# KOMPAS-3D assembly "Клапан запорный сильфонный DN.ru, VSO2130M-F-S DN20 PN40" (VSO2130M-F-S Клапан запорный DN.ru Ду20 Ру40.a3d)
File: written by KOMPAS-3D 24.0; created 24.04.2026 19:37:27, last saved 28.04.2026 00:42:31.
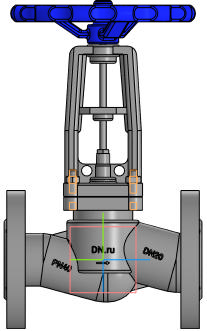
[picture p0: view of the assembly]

Document properties: Автор: DN.ru; Полное имя файла: C:\Работа\ГОТОВЫЕ ИСХОДНИКИ\VSO2130M-F-S Клапан запорный сильфонный DN.ru Ду15-100 Ру40\исходные материалы\DN20\VSO2130M-F-S Клапан запорный DN.ru Ду20 Ру40.a3d

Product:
- Component [detail]: Корпус  | qty 1  | pos. 1  | Масса: 6.9; Автор: R2D2; source file: Korpus.m3d
- Component [detail]: Деталь  | qty 1  | pos. 2  | Масса: 0.70221; Автор: mrdid; source file: rama.m3d
- Component [detail]: Деталь2  | qty 1  | pos. 3  | Масса: 0.594157; Автор: R2D2; additional columns: Типовые; source file: shturval.m3d
- Component [standard]: Шпилька М6-6gx25 ГОСТ 22032-76  | qty 4  | Масса: 0.005789; Раздел спецификации: Стандартные изделия; Рассекать на разрезах: no
- Component [standard]: Гайка М6-6H ГОСТ 5915-70  | qty 4  | Масса: 0.002573; Раздел спецификации: Стандартные изделия; Рассекать на разрезах: no
- Part/product: Клапан запорный сильфонный DN.ru  | designation VSO2130M-F-S DN20 PN40
    Масса: 5
    Раздел спецификации: Прочие изделия
    Примечание: D090-01971

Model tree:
1. Контекстная связь:1  (with: Эскиз:2, Ребро.Элемент выдавливания:14, Контекстная связь (Деталь):1)
2. Контекстная связь:2  (with: Контекстная связь (Деталь):2)
3. Массив по концентрической сетке:1  (with: Грань.Элемент выдавливания:1, Грань.Элемент выдавливания:15, Грань.Элемент выдавливания:3, Грань.Элемент выдавливания:2, Грань.Элемент выдавливания:16, Грань.Элемент выдавливания:17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)  (labels: Грань.Твердое тело1)  (4 pattern instances)
     Шаг 2 = 360; Угол = 7

Referenced files in C:\Работа\ГОТОВЫЕ ИСХОДНИКИ\VSO2130M-F-S Клапан запорный сильфонный DN.ru Ду15-100 Ру40\исходные материалы\DN20\: Korpus.m3d, rama.m3d, shturval.m3d
Referenced files in C:\Program Files\ASCON\KOMPAS-3D v24\Libs\PolynomLib\DATA\vault\Methods\Kompas\3D\: PLib_Stud_1_900.m3d, PLib_Nut_OST92_900.m3d
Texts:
  BOSimple***PART:e489ae6d-d315-b2e9-dd59-4407119351be***SHORTLOC:Root±30±20±10±120±10±20[Нет;Без покрытия;Без указания материала;-;6;25;1;1]
  Крепежное изделие ГОСТ
  BOSimple***PART:832b7c99-94b5-75d7-382c-73b3a2f1c6df***SHORTLOC:Root±30±10±20±©{}110±10±50±60[Нет;Без покрытия;Без указания материала;-;6;1;10]
  Программные изделия  и базы данных
  VSO2130M-F-S DN20 PN40
  Деталь2 Деталь2
  Шпилька М6-6gx25 ГОСТ 22032-76 (1)
  cut1
  Гайка М6-6H ГОСТ 5915-70 (1)
  bcut1
  hole1
  hcut1
  hole2
  Шпилька М6-6gx25 ГОСТ 22032-76 (2)
  Гайка М6-6H ГОСТ 5915-70 (2)
  Шпилька М6-6gx25 ГОСТ 22032-76 (3)
  Гайка М6-6H ГОСТ 5915-70 (3)
  Шпилька М6-6gx25 ГОСТ 22032-76 (4)
  Гайка М6-6H ГОСТ 5915-70 (4)
  Plane. Начало координат
  Плоскость XY.Начало координат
